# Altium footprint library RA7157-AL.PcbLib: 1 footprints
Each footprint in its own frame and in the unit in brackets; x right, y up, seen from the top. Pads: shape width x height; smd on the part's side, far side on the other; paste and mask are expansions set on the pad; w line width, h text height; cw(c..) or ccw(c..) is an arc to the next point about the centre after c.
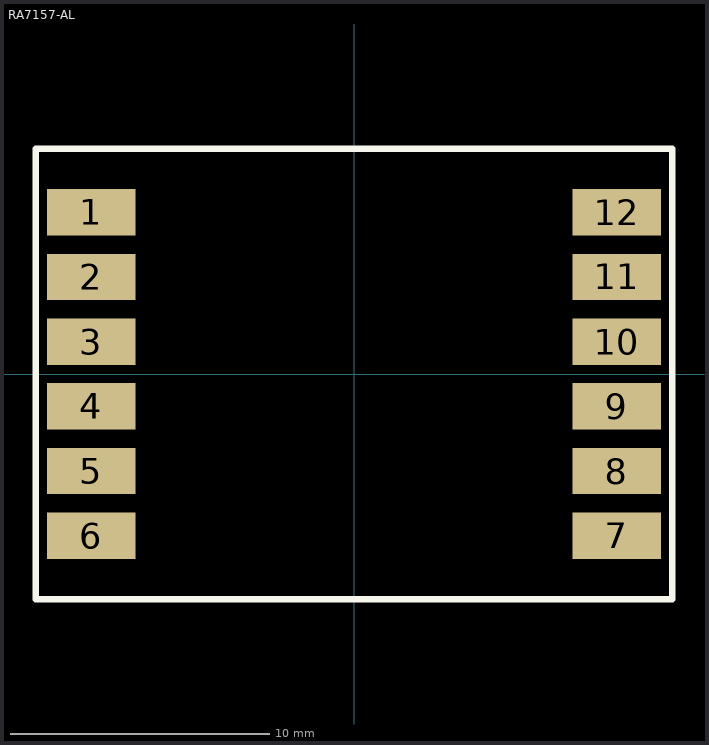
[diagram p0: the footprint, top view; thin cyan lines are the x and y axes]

## RA7157-AL [mm] "COILCRAFT RA7157-AL CUSTOM TRANSFORMER"
height 8.65
pads (13):
  round 1.524 on Top Overlay: 0(-6.9,6.2)
  rect 3.43x1.79 smd: 1(-10.155,6.25) 2(-10.155,3.75) 3(-10.155,1.25) 4(-10.155,-1.25) 5(-10.155,-3.75) 6(-10.155,-6.25) 7(10.155,-6.25) 8(10.155,-3.75) 9(10.155,-1.25) 10(10.155,1.25) 11(10.155,3.75) 12(10.155,6.25)
Top Overlay:
  lines w0.254: -12.3,-8.7 12.3,-8.7 12.3,8.7 -12.3,8.7 -12.3,-8.7
M5 Assembly Top:
  text ".Designator" at 0,-0.1 h1.02
3D body: height 8.65, standoff 0, extent -12.3,-8.7 12.3,8.7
